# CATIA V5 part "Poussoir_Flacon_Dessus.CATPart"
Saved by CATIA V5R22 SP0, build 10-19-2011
Part number: Poussoir_Flacon_Dessus
Bounding box of the stored display mesh (mm): x -90 to 90, y -20 to 20, z 0 to 5
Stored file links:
  C:\Users\La forge\Desktop\CAO_PER_pick&place_2023A\Sous_Ensemble_Flacon\Verin\Poussoir_Flacon\Poussoir_Flacon_Dessus.CATPart
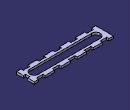
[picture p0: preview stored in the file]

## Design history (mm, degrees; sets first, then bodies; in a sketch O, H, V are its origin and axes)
Body1 (main body)
  Sketch1 on xy-plane, origin (0, 0, 0), H (1, 0, 0), V (0, 1, 0)
    line L1 (90, -20) -> (-90, -20)
    line L2 (-90, -20) -> (-90, 20)
    line L3 (-90, 20) -> (90, 20)
    line L4 (90, 20) -> (90, -20)
    point P5 (80, -10)
    line L5 (70, -10) -> (-70, -10)
    line L6 (-80, 0) -> (-80, 0)
    line L7 (-70, 10) -> (70, 10)
    line L8 (80, 0) -> (80, 0)
    point P6 (-80, -10)
    point P7 (-80, 10)
    point P8 (80, 10)
    arc A1 centre (-70, 0) radius 10 from (-80, 0) to (-70, 10) cw
    arc A2 centre (70, 0) radius 10 from (70, 10) to (80, 0) cw
    arc A3 centre (70, 0) radius 10 from (80, 0) to (70, -10) cw
    arc A4 centre (-70, 0) radius 10 from (-70, -10) to (-80, 0) cw
    length L3 = 180
    length L4 = 40
    distance L4 L8 = 10
    distance L5 L1 = 10
    radius A1 = 10
    radius A2 = 10
    radius A3 = 10
    radius A4 = 10
    horizontal: L1 H, L3 H, L5 H, L7 H
    vertical: L2 V, L4 V, L6 V, L8 V
    equidistance: L4 L2 O, L1 L3 O, P8 P6 O, P5 P7 O
    coincidence: L6 P7, L7 P7, L7 P8, L8 P8, L8 P5, L5 P5, L5 P6, L6 P6
    tangency: A1 L6, A1 L7, A2 L7, A2 L8, A3 L8, A3 L5, A4 L5, A4 L6
  Pad1: profile Sketch1, direction (0, 0, 1), length 5
  Sketch2 on end face of Pad1, origin (0, 0, 5), H (1, 0, 0), V (0, 1, 0)
    line L1 (90, 5) -> (85, 5)
    line L2 (85, 5) -> (85, -5)
    line L3 (85, -5) -> (90, -5)
    line L4 (90, -5) -> (90, 5)
    reference projected line E1 (90, -20) -> (90, 20) from edge [face of Pad1 from Sketch1.L4 | end face of Pad1]
    reference projected line E2 (-90, -20) -> (90, -20) from edge [face of Pad1 from Sketch1.L1 | end face of Pad1]
    length L1 = 5
    distance L3 E2 = 15
    horizontal: L1 H, L3 H
    vertical: L2 V, L4 V
    equidistance: L3 L1 O
    coincidence: L4 E1
  Pocket1: profile Sketch2, direction (0, 0, -1), through (limit type 6)
  Sketch3 on end face of Pad1, origin (0, 0, 5), H (1, 0, 0), V (0, 1, 0)
    point P1 (-7.5, -20)
    line L1 (-7.5, -20) -> (7.5, -20)
    line L2 (7.5, -20) -> (7.5, -15)
    line L3 (7.5, -15) -> (-7.5, -15)
    line L4 (-7.5, -15) -> (-7.5, -20)
    point P2 (7.5, -20)
    point P3 (7.5, -15)
    point P4 (-7.5, -15)
    reference projected line E1 (-90, -20) -> (90, -20) from edge [face of Pad1 from Sketch1.L1 | end face of Pad1]
    point P5 (65, -20)
    line L5 (65, -20) -> (80, -20)
    line L6 (80, -20) -> (80, -15)
    line L7 (80, -15) -> (65, -15)
    line L8 (65, -15) -> (65, -20)
    point P6 (80, -20)
    point P7 (80, -15)
    point P8 (65, -15)
    reference projected line E2 (90, -20) -> (90, 20) from edge [face of Pad1 from Sketch1.L4 | end face of Pad1]
    point P9 (-65, -20)
    point P10 (-80, -20)
    point P11 (-80, -15)
    point P12 (-65, -15)
    line L9 (-65, -20) -> (-80, -20)
    line L10 (-80, -20) -> (-80, -15)
    line L11 (-80, -15) -> (-65, -15)
    line L12 (-65, -15) -> (-65, -20)
    point P13 (-7.5, 20)
    point P14 (7.5, 20)
    point P15 (7.5, 15)
    point P16 (-7.5, 15)
    point P17 (65, 20)
    point P18 (80, 20)
    point P19 (80, 15)
    point P20 (65, 15)
    point P21 (-65, 20)
    point P22 (-80, 20)
    point P23 (-80, 15)
    point P24 (-65, 15)
    line L13 (-7.5, 20) -> (7.5, 20)
    line L14 (7.5, 20) -> (7.5, 15)
    line L15 (7.5, 15) -> (-7.5, 15)
    line L16 (-7.5, 15) -> (-7.5, 20)
    line L17 (65, 20) -> (80, 20)
    line L18 (80, 20) -> (80, 15)
    line L19 (80, 15) -> (65, 15)
    line L20 (65, 15) -> (65, 20)
    line L21 (-65, 20) -> (-80, 20)
    line L22 (-80, 20) -> (-80, 15)
    line L23 (-80, 15) -> (-65, 15)
    line L24 (-65, 15) -> (-65, 20)
    construction line L25 (-18.125, 30) -> (-18.125, -30.0944)
    axis line L26 (18.125, 30) -> (18.125, -30)
    point P29 (36.25, 0)
    point P30 (43.75, -20)
    point P31 (28.75, -20)
    point P32 (28.75, -15)
    point P33 (43.75, -15)
    point P34 (43.75, 20)
    point P35 (28.75, 20)
    point P36 (28.75, 15)
    point P37 (43.75, 15)
    line L27 (43.75, -20) -> (28.75, -20)
    line L28 (28.75, -20) -> (28.75, -15)
    line L29 (28.75, -15) -> (43.75, -15)
    line L30 (43.75, -15) -> (43.75, -20)
    line L31 (43.75, 20) -> (28.75, 20)
    line L32 (28.75, 20) -> (28.75, 15)
    line L33 (28.75, 15) -> (43.75, 15)
    line L34 (43.75, 15) -> (43.75, 20)
    point P38 (-28.75, -20)
    point P39 (-43.75, -20)
    point P40 (-43.75, -15)
    point P41 (-28.75, -15)
    point P42 (-28.75, 20)
    point P43 (-43.75, 20)
    point P44 (-43.75, 15)
    point P45 (-28.75, 15)
    line L35 (-28.75, -20) -> (-43.75, -20)
    line L36 (-43.75, -20) -> (-43.75, -15)
    line L37 (-43.75, -15) -> (-28.75, -15)
    line L38 (-28.75, -15) -> (-28.75, -20)
    line L39 (-28.75, 20) -> (-43.75, 20)
    line L40 (-43.75, 20) -> (-43.75, 15)
    line L41 (-43.75, 15) -> (-28.75, 15)
    line L42 (-28.75, 15) -> (-28.75, 20)
    length L2 = 5
    length L3 = 15
    length L7 = 15
    distance E2 L6 = 10
    distance L25 V = 18.125
    distance V L26 = 18.125
    horizontal: L1 H, L3 H, L5 H, L7 H
    vertical: L2 V, L4 V, L6 V, L8 V, L25 V, L26 V
    coincidence: L1 E1, P5 L1, L7 L3
    equidistance: L4 L2 O
    symmetry: P5 P9 V, P6 P10 V, P7 P11 V, P8 P12 V, L5 L9 V, L6 L10 V, L7 L11 V, L8 L12 V, P1 P13 H, P2 P14 H, P3 P15 H, P4 P16 H, P5 P17 H, P6 P18 H, P7 P19 H, P8 P20 H, P9 P21 H, P10 P22 H, P11 P23 H, P12 P24 H, L1 L13 H, L2 L14 H, L3 L15 H, L4 L16 H, L5 L17 H, L6 L18 H, L7 L19 H, L8 L20 H, L9 L21 H, L10 L22 H, L11 L23 H, L12 L24 H, O P29 L26, P1 P30 L26, P2 P31 L26, P3 P32 L26, P4 P33 L26, P13 P34 L26, P14 P35 L26, P15 P36 L26, P16 P37 L26, L1 L27 L26, L2 L28 L26, L3 L29 L26, L4 L30 L26, L13 L31 L26, L14 L32 L26, L15 L33 L26, L16 L34 L26, P1 P38 L25, P2 P39 L25, P3 P40 L25, P4 P41 L25, P13 P42 L25, P14 P43 L25, P15 P44 L25, P16 P45 L25, L1 L35 L25, L2 L36 L25, L3 L37 L25, L4 L38 L25, L13 L39 L25, L14 L40 L25, L15 L41 L25, L16 L42 L25
  Pocket2: profile Sketch3, direction (0, 0, -1), through (limit type 6)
